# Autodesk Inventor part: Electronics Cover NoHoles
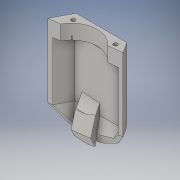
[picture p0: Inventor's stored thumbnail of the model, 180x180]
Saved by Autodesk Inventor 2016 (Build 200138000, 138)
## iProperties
Created: 2015-09
Part Number: Electronics Cover NoHoles
Material: Generic
Document SubType Name: Modeling
Designer: Z
Density: 1 g/cm^3
Appearance: Default
Author: Z
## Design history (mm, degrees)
derived "cane mount.ipt"
  sketch "Sketch37"
    geometry: L1 (7.76, 0)-(8.043, 0) reference; L2 (19.064, 57.15)-(19.064, 0) reference; L3 (15.314, 0)-(15.314, 50.8) reference; L4 (15.314, 50.8)-(8.043, 50.8) reference; L5 (8.043, 0)-(8.043, 50.8) reference; L6 (8.043, 57.15)-(19.064, 57.15) reference; L7 (8.043, 50.8)-(8.043, 57.15) reference; L8 (0, 50.8)-(0, 0) reference; L9 (7.76, 50.8)-(7.76, 0) reference; L10 (7.76, 50.8)-(0, 50.8) reference; L11 (-3.767, 0)-(-3.767, 63.5) reference; L12 (-3.767, 63.5)-(7.76, 63.5) reference; L13 (7.76, 63.5)-(7.76, 50.8) reference; L14 (15.314, 3.175)-(0, 3.175) reference; L15 (0, 3.175)-(0, 15.875) reference; L16 (0, 15.875)-(15.314, 15.875) reference; L17 (15.314, 15.875)-(15.314, 3.175) reference; L18 (22.176, 138.821)-(22.176, 57.15) reference; L19 (22.176, 57.15)-(8.043, 57.15) reference; L20 (8.043, 57.15)-(8.043, 63.5) reference; L21 (8.043, 63.5)-(20.939, 63.5) reference; L22 (20.939, 63.5)-(20.939, 131.401) reference; L23 (19.064, 63.5)-(-3.767, 63.5) reference; L24 (-3.767, 63.5)-(-3.767, 79.375) reference; L25 (-3.767, 79.375)-(0, 79.375) reference; L26 (0, 79.375)-(0, 73.025) reference; L27 (0, 73.025)-(1.04, 73.025) reference; L28 (1.04, 73.025)-(1.04, 69.85) reference; L29 (1.04, 69.85)-(2.439, 69.85) reference; L30 (2.439, 69.85)-(2.439, 73.025) reference; L31 (2.439, 73.025)-(12.859, 73.025) reference; L32 (12.859, 73.025)-(12.859, 69.85) reference; L33 (12.859, 69.85)-(14.259, 69.85) reference; L34 (14.259, 69.85)-(14.259, 73.025) reference; L35 (14.259, 73.025)-(12.859, 73.025) reference; L36 (19.064, 79.375)-(19.064, 63.5) reference; L37 (15.314, 79.375)-(19.064, 79.375) reference; L38 (15.314, 73.025)-(15.314, 79.375) reference; L39 (14.259, 73.025)-(15.314, 73.025) reference; L40 (0, 79.375)-(15.314, 79.375) reference; L41 (2.439, 73.025)-(1.04, 73.025) reference; L42 (20.939, 131.401)-(15.621, 141.446) reference; L43 (15.621, 141.446)-(8.043, 140.562) reference; L44 (8.043, 140.562)-(8.043, 149.786) reference; L45 (8.043, 149.786)-(15.887, 150.702) reference; L46 (15.887, 150.702)-(22.176, 138.821) reference; 5 further points
  sketch "Sketch38"
    geometry: L1 (-12.361, 64.822)-(-4.847, 64.822) reference; L2 (-4.847, 64.822)-(7.871, 9.897) reference; L3 (7.871, 9.897)-(5.044, 0.782) reference; L4 (-56.252, 0.782)-(-58.671, 11.761) reference; L5 (-58.671, 11.761)-(-43.805, 64.822) reference; L6 (-43.805, 64.822)-(-37.173, 64.822) reference; L7 (-40.964, 57.706)-(-42.061, 57.706) reference; L8 (-42.061, 57.706)-(-55.048, 11.353) reference; L9 (-55.048, 11.353)-(-52.719, 0.782) reference; L10 (1.192, 0.782)-(4.181, 10.421) reference; L11 (4.181, 10.421)-(-6.768, 57.706) reference; L12 (-6.768, 57.706)-(-8.569, 57.706) reference; L13 (-24.767, 23.835)-(-24.767, -28.939) reference; L14 (-4.847, 64.822)-(-20.015, 64.822) reference; L15 (-29.519, 64.822)-(-43.805, 64.822) reference; L16 (-43.805, 64.822)-(-41.812, 71.937) reference; L17 (-29.752, 71.937)-(-41.812, 71.937) reference; L18 (-41.812, 71.937)-(-40.173, 77.786) reference; L19 (-40.173, 77.786)-(-7.62, 76.797) reference; L20 (-7.62, 76.797)-(-6.494, 71.937) reference; L21 (-6.494, 71.937)-(-27.031, 71.937) reference; L22 (-27.031, 71.937)-(-27.077, 72.924) reference; L23 (-41.812, 71.937)-(-6.494, 71.937) reference; L24 (-6.494, 71.937)-(-4.847, 64.822) reference; C1 r 1.5 at (-24.767, -22.589) reference; 16 further points; 5 other entities
    constraints: 5 other
  sketch "Sketch39"
    geometry: L1 (-25.388, 57.15)-(-14.362, 57.15) reference; L2 (-14.362, 57.15)-(-14.362, 50.8) reference; L3 (-14.362, 50.8)-(-14.362, 0) reference; L4 (-14.362, 0)-(-14.4, 0) reference; L5 (-21.781, 50.8)-(-21.781, 0) reference; L6 (-14.362, 50.8)-(-21.781, 50.8) reference; L7 (-25.388, 0.007)-(-25.388, 57.15) reference; L8 (-14.4, 0)-(-7.597, -10.524) reference; L9 (-7.597, -10.524)-(-14.054, 0) reference; L10 (0, 50.8)-(-14.054, 50.8) reference; L11 (-14.054, 0)-(-14.054, 50.8) reference; L12 (-14.054, 50.8)-(-14.054, 63.5) reference; L13 (-14.054, 63.5)-(3.595, 63.5) reference; L14 (3.595, 63.5)-(3.595, 0.004) reference; L15 (0, 0)-(0, 50.8) reference; L16 (-21.781, 25.4)-(0, 25.4) reference; L17 (0, 25.4)-(0, 6.35) reference; L18 (0, 6.35)-(-21.781, 6.35) reference; L19 (-21.781, 6.35)-(-21.781, 25.4) reference; L20 (3.595, 63.5)-(-25.388, 63.5) reference; L21 (-25.388, 63.5)-(-25.388, 79.375) reference; L22 (-25.388, 79.375)-(-20.626, 79.375) reference; L23 (-20.626, 79.375)-(-20.626, 73.025) reference; L24 (-20.626, 73.025)-(-20.585, 73.025) reference; L25 (-19.186, 73.025)-(-20.585, 73.025) reference; L26 (-19.186, 69.85)-(-19.186, 73.025) reference; L27 (-20.585, 69.85)-(-19.186, 69.85) reference; L28 (-20.585, 73.025)-(-20.585, 69.85) reference; L29 (3.595, 79.375)-(3.595, 63.5) reference; L30 (0, 79.375)-(3.595, 79.375) reference; L31 (0, 73.025)-(0, 79.375) reference; L32 (-1.21, 73.025)-(0, 73.025) reference; L33 (-1.21, 73.025)-(-2.609, 73.025) reference; L34 (-19.186, 73.025)-(-2.609, 73.025) reference; L35 (-20.626, 79.375)-(0, 79.375) reference; L36 (-1.21, 69.85)-(-1.21, 73.025) reference; L37 (-2.609, 69.85)-(-1.21, 69.85) reference; L38 (-2.609, 73.025)-(-2.609, 69.85) reference; L39 (-14.362, 63.5)-(-14.362, 57.15) reference; L40 (-14.362, 57.15)-(-29.773, 57.15) reference; L41 (-29.773, 57.15)-(-29.773, 141.139) reference; L42 (-29.773, 141.139)-(-21.02, 155.677) reference; L43 (-21.02, 155.677)-(-14.362, 154.568) reference; L44 (-14.362, 154.568)-(-14.362, 146.396) reference; L45 (-14.362, 146.396)-(-21.35, 147.56) reference; L46 (-21.35, 147.56)-(-27.191, 137.858) reference; L47 (-27.191, 137.858)-(-27.191, 63.5) reference; L48 (-27.191, 63.5)-(-14.362, 63.5) reference; 3 further points
sketch "Sketch4"
  geometry: L1 (1.109, 50.8)-(1.109, 63.5) reference; L2 (1.109, 63.5)-(22.333, 63.5) reference; L3 (22.333, 63.5)-(22.333, 0) reference; L4 (10.368, -15.64)-(-12.495, -20.794) reference; L5 (-25.465, 0.001)-(-25.465, 63.5) reference; L6 (-25.465, 63.5)-(-6.375, 63.5) reference; L7 (-6.375, 63.5)-(-6.375, 50.8) reference; L8 (-6.375, 50.8)-(1.109, 50.8) reference; L9 (18.566, 50.8)-(1.109, 50.8) reference; L10 (18.566, 0)-(18.566, 50.8) reference; L11 (0, 9.242)-(0, 0) reference; L12 (-15.471, 10.134)-(0, 9.242) reference; L13 (-15.471, 0)-(-15.471, 10.134) reference; L14 (-21.871, 50.8)-(-21.871, 0) reference; L15 (-6.375, 50.8)-(-21.871, 50.8) reference; L16 (-6.732, 19.05)-(-19.432, 19.05); L17 (-19.432, 19.05)-(-19.432, 12.7); L18 (-19.432, 12.7)-(-6.732, 12.7); L19 (-6.732, 12.7)-(-6.732, 19.05); L20 (16.128, 19.05)-(3.428, 19.05); L21 (3.428, 19.05)-(3.428, 12.7); L22 (3.428, 12.7)-(16.128, 12.7); L23 (16.128, 12.7)-(16.128, 19.05); L24 (-21.871, 25.4)-(18.566, 25.4); L25 (-1.652, 25.4)-(-1.652, 0); L26 (-21.871, 0)-(18.566, 0); L27 (-6.732, 12.7)-(-1.652, 12.7); L28 (3.428, 12.7)-(-1.652, 12.7); 4 further points
  constraints: 26 end point, 5 equal length, 5 midpoint, 3 horizontal, 2 collinear, 2 horizontal alignment, 2 perpendicular, 2 point on line, 1 vertical, 5 other
  dimensions: "d1" = 12.7 distance of L17.end L18.end; "d2" = 10.16 distance between parallel lines of L21 L19; "d3" = 6.35 distance of L16.end L17.end
extrude "Extrusion1" cut sketch "Sketch4" stored distance "d4" = 25.4; taper "d5" = 0 deg
feature "Solid17::cane mount.ipt" dims "d0" = 10
tag "TaggingFeature1"
workplane "Work Plane6"
workplane "Work Plane7"
workplane "Work Plane14"
workaxis "Work Axis2"
body "Solid1"
node "Project Cut Edges1"
